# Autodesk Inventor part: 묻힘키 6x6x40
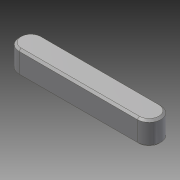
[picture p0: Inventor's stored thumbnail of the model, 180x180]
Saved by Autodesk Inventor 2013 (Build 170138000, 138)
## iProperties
Created: 2013-07
Part Number: 묻힘키 6x6x40
Document SubType Name: Modeling
Designer: SeoGD™[esajin.kr]
Density: 1 g/cm^3
Mass: 1.24965 g
Surface Area: 8.89646 cm^2
Volume: 1.24965 cm^3
Material: 강철, 연강
Author: SeoGD™[esajin.kr]
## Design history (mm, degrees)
sketch "스케치1"
  geometry: L1 (15, 3)-(-19, 3) reference; L2 (-19, -3)-(15, -3) reference; A1 r 3 centre (15, 0) between (15, -3) and (15, 3) reference; A2 r 3 centre (-19, 0) between (-19, 3) and (-19, -3) reference
extrude "돌출1" new body sketch "스케치1" distance "d0" = 6; taper "d1" = 0 deg
chamfer "모따기1" distance "d2" = 0.5; stored, may be unused: second distance "d3" = 2, angle "d4" = 45 deg
node "솔리드1"
node "참조5"
